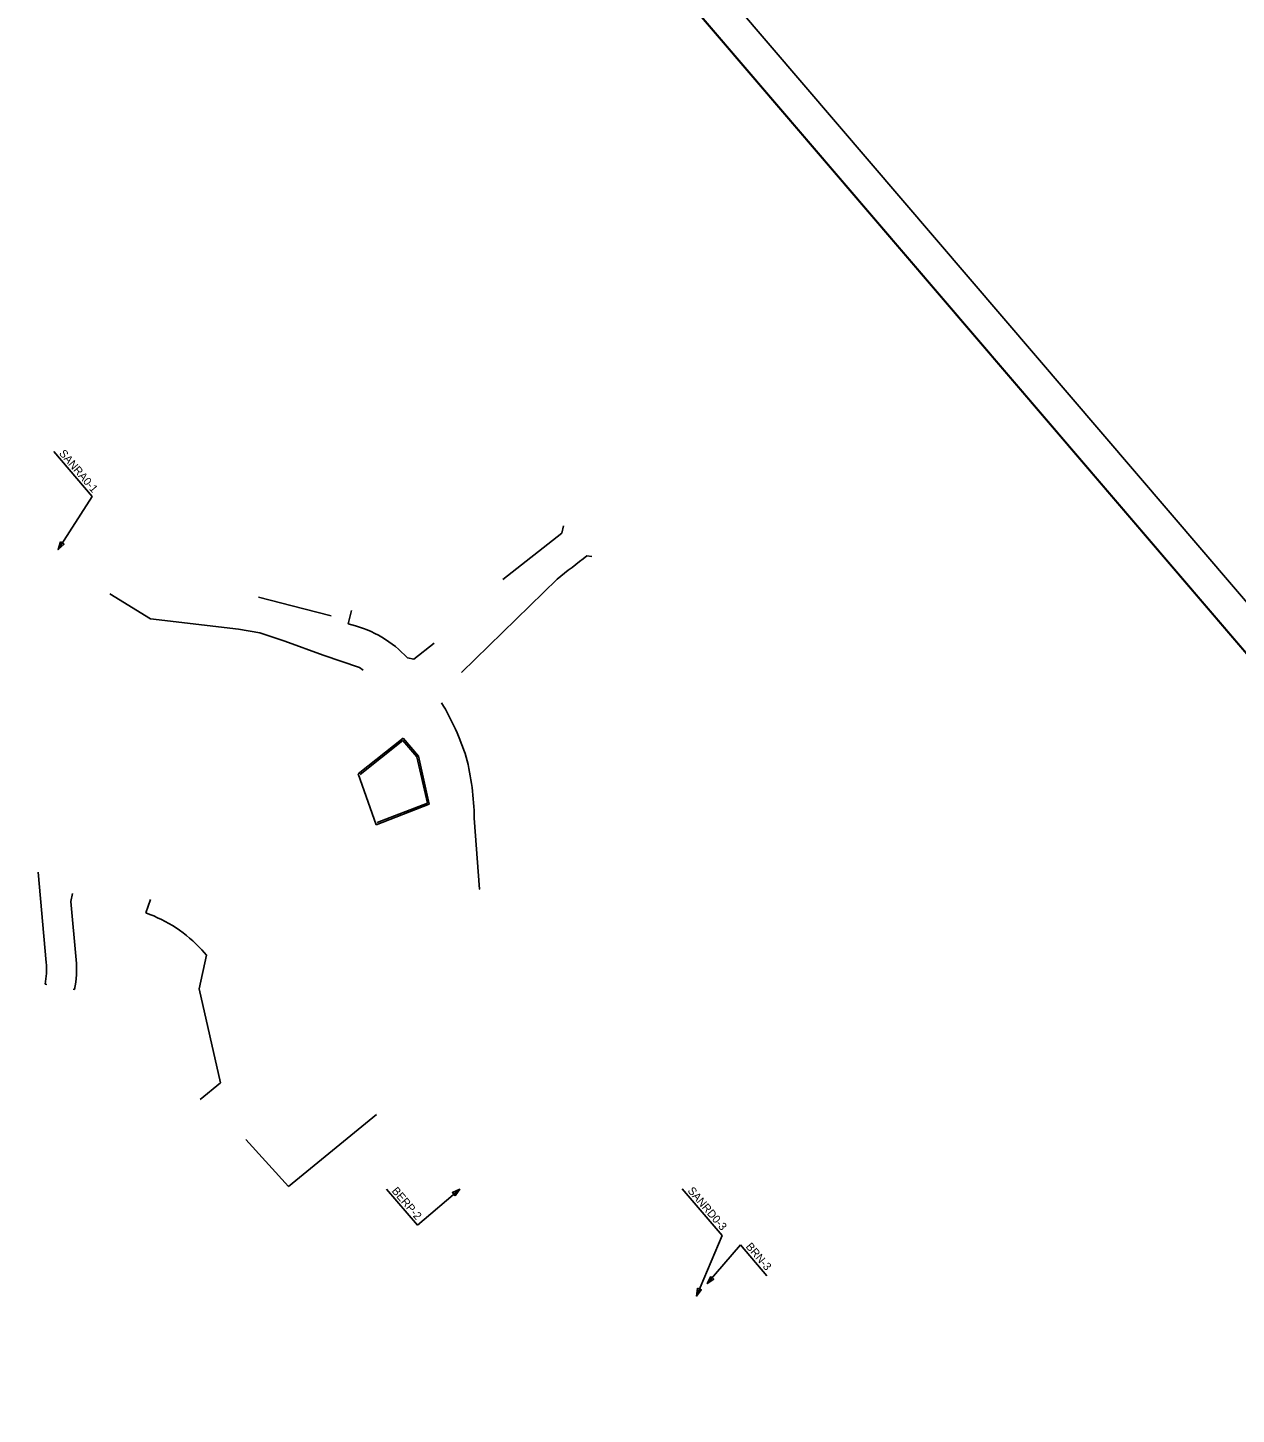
# Model space of a CAD drawing. Extents: x 1941897 to 1978064, y 805467 to 836604.
# Drawn here: x 1953062 to 1956688, y 821550 to 825709 of the extents above; entities that cross this region are included whole.
import ezdxf

# ---------------------------------------------------------------- set-up
doc = ezdxf.new("R2010")
doc.units = 0
for name, color, linetype in [('RD_EX_H20_TX', 7, 'Continuous'), ('RD_PD_Control_Access', 7, 'Continuous'), ('RD_PD_RW', 7, 'Continuous'), ('RD_SHT_Bndy', 7, 'Continuous'), ('RD_SHT_IplotShp', 7, 'Continuous'), ('RD_TX_RoadID', 7, 'Continuous')]:
    doc.layers.add(name, color=color, linetype=linetype)

msp = doc.modelspace()

# ---------------------------------------------------------------- linework, layer by layer
at = {"layer": 'RD_EX_H20_TX'}
for points in [[(1963151.2, 810860.3), (1959509.3, 815114.3), (1958096.8, 813905.1), (1957040.5, 814307.7), (1947588.1, 825348.6), (1952108, 829218.2), (1965848, 813169.1)], [(1963151.2, 810860.3), (1959509.3, 815114.3), (1958096.8, 813905.1), (1957040.5, 814307.7), (1947588.1, 825348.6), (1952108, 829218.2), (1965848, 813169.1)], [(1963151.2, 810860.3), (1959509.3, 815114.3), (1958096.8, 813905.1), (1957040.5, 814307.7), (1947588.1, 825348.6), (1952108, 829218.2), (1965848, 813169.1)], [(1963151.2, 810860.3), (1959509.3, 815114.3), (1958096.8, 813905.1), (1957040.5, 814307.7), (1949323.3, 823321.8), (1953668.8, 827395), (1965848, 813169.1)], [(1963151.2, 810860.3), (1959509.3, 815114.3), (1958096.8, 813905.1), (1957040.5, 814307.7), (1949323.3, 823321.8), (1953668.8, 827395), (1965848, 813169.1)], [(1963151.2, 810860.3), (1959509.3, 815114.3), (1958096.8, 813905.1), (1957040.5, 814307.7), (1949323.3, 823321.8), (1953668.8, 827395), (1965848, 813169.1)]]:
    msp.add_lwpolyline(points, close=True, dxfattribs=at)
at = {"layer": 'RD_PD_Control_Access'}
for p, q in [((1953308.6, 824011.6), (1953430.4, 823936.1)), ((1953430.4, 823936.1), (1953694.5, 823904.9)), ((1954188.6, 823578.2), (1954053.2, 823471)), ((1954188.6, 823578.2), (1954234.4, 823524.8)), ((1954266.9, 823380.6), (1954234.4, 823524.8)), ((1954053.2, 823471), (1954107.1, 823318.6)), ((1954266.9, 823380.6), (1954107.1, 823318.6))]:
    msp.add_line(p, q, dxfattribs=at)
msp.add_lwpolyline([(1953694.5, 823904.9), (1953758.7, 823894.1), (1953833.6, 823869), (1953948.1, 823826.9), (1954057.8, 823790.5), (1954068.9, 823781.9)], dxfattribs=at)
at = {"layer": 'RD_PD_RW'}
for p, q in [((1954669.2, 824215.6), (1954665, 824193.4)), ((1954665, 824193.4), (1954487.6, 824054.2)), ((1954754.5, 824123.4), (1954740.1, 824125.1)), ((1954363.9, 823775.4), (1954650.9, 824055.4)), ((1953754.7, 824001.5), (1953890.3, 823966.7)), ((1953890.3, 823966.7), (1953972.7, 823945.6)), ((1954033.3, 823961.1), (1954023.2, 823921.3)), ((1954023.2, 823921.3), (1954034.1, 823918.5)), ((1954281.9, 823863.1), (1954220.6, 823815.6)), ((1954201.4, 823819.1), (1954220.6, 823815.6)), ((1954188, 823571.3), (1954059.1, 823469.3)), ((1954188, 823571.3), (1954229.8, 823522.5)), ((1954261.1, 823383.7), (1954229.8, 823522.5)), ((1954261.1, 823383.7), (1954110.1, 823325.1)), ((1954401.7, 823338.5), (1954417.9, 823125.2)), ((1953093.2, 823176.6), (1953117.6, 822905.2)), ((1954416.3, 823125.1), (1954417.9, 823125.2)), ((1953191.6, 823088), (1953196.2, 823112.1)), ((1953191.6, 823088), (1953207.3, 822913.2)), ((1953416.6, 823054.2), (1953430.8, 823094.8)), ((1953598.3, 822927.9), (1953576.7, 822826.9)), ((1953584.4, 822943.3), (1953598.3, 822927.9)), ((1953114.6, 822841), (1953119.5, 822840)), ((1953198.1, 822825.3), (1953203, 822824.4)), ((1953576.7, 822826.9), (1953640.6, 822544.9)), ((1953640.6, 822544.9), (1953579.2, 822494.7)), ((1953844.9, 822233.9), (1954108.2, 822449.8)), ((1953716.9, 822374.6), (1953844.9, 822233.9))]:
    msp.add_line(p, q, dxfattribs=at)
for centre, radius, start, end in [((1956429.1, 821873.2), 2814.9, 126.8722, 129.1765), ((1953948.4, 823583.9), 345.5, 42.9201, 75.6347), ((1953634.9, 823281.3), 781, 17.924, 31.0625), ((1953629.8, 823331.4), 771.9, 0.5286, 14.2659), ((1953281.3, 822667.2), 410, 42.3283, 70.7261), ((1952883.6, 822884.1), 235, 349.4083, 5.1333), ((1952883.6, 822884.1), 325, 349.4083, 5.1333)]:
    msp.add_arc(centre, radius, start, end, dxfattribs=at)
at = {"layer": 'RD_SHT_Bndy'}
msp.add_lwpolyline([(1960707.9, 808409.5), (1943668.8, 828312), (1948986.3, 832864.4), (1966025.3, 812961.9)], close=True, dxfattribs=at)
at = {"layer": 'RD_SHT_IplotShp'}
msp.add_lwpolyline([(1960696.9, 808268.5), (1943527.9, 828323), (1948997.3, 833005.4), (1966166.3, 812950.9)], close=True, dxfattribs=at)
at = {"layer": 'RD_TX_RoadID'}
for p, q in [((1953255.8, 824302.9), (1953140.2, 824437.9)), ((1954231.1, 822117.4), (1954138.4, 822225.7)), ((1955145.2, 822087), (1955026, 822226.2)), ((1955280, 821965.6), (1955200.4, 822058.6))]:
    msp.add_line(p, q, dxfattribs=at)
for points in [[(1953255.8, 824302.9), (1953153.3, 824143.9)], [(1954231.1, 822117.4), (1954358.1, 822225.6)], [(1955145.2, 822087), (1955068.4, 821904.9)], [(1955200.4, 822058.6), (1955100.8, 821942.5)]]:
    msp.add_lwpolyline(points, dxfattribs=at)
for points in [[(1953160.7, 824166.8), (1953153.3, 824143.9), (1953171.1, 824160.1)], [(1954344.4, 822205.8), (1954358.1, 822225.6), (1954336.4, 822215.3)], [(1955111.2, 821964.1), (1955100.8, 821942.5), (1955120.6, 821956.1)], [(1955071.7, 821928.6), (1955068.4, 821904.9), (1955083.1, 821923.8)]]:
    msp.add_lwpolyline(points, close=True, dxfattribs=at)

# ---------------------------------------------------------------- texts
for s, p in [('SANRA0-1', (1953154.7, 824431.8)), ('BERP-2', (1954152.8, 822219.6)), ('SANRD0-3', (1955040.5, 822220.1)), ('BRN-3', (1955214.8, 822052.6))]:
    msp.add_text(s, height=24, rotation=310.5675, dxfattribs=at).set_placement(p)

doc.saveas('drawing.dxf')
